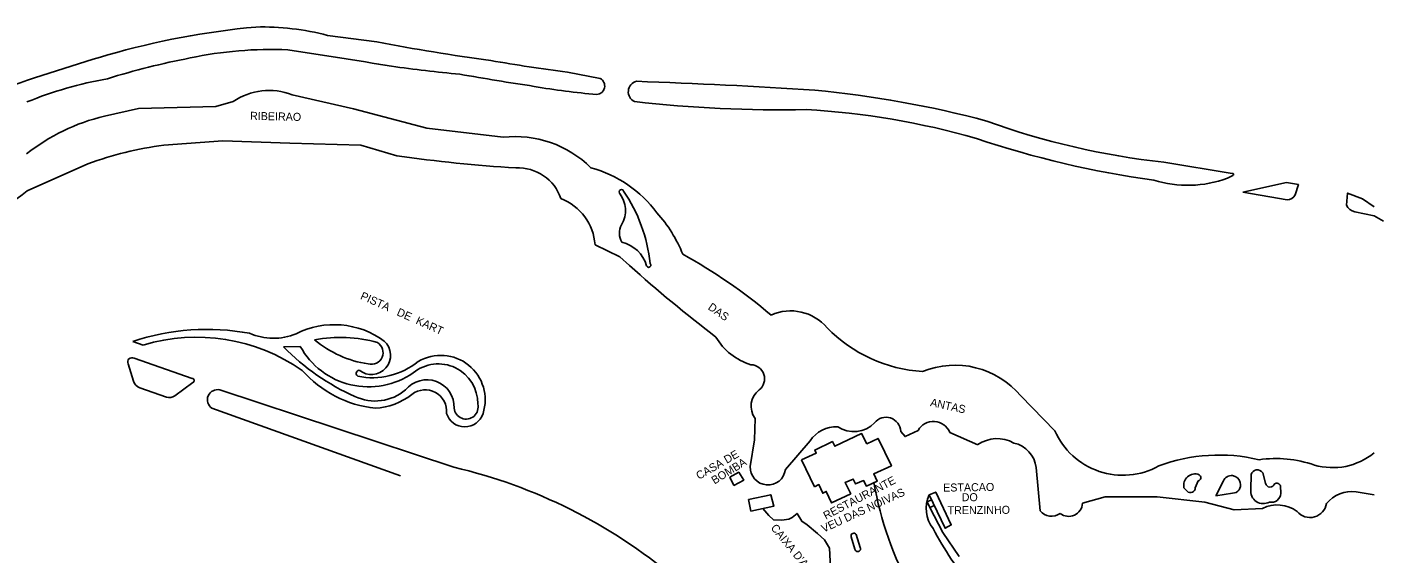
# Model space of a CAD drawing. Extents: x 325899 to 363134, y 7578590 to 7592502.
# Drawn here: x 333008 to 333681, y 7591049 to 7591312 of the extents above; entities that cross this region are included whole.
import ezdxf

# ---------------------------------------------------------------- set-up
doc = ezdxf.new("R2010")
doc.units = 0
for name, color, linetype in [('EDIFEXISTENT', 7, 'Continuous'), ('EDIFIDENTIF', 7, 'Continuous'), ('EDIFOBRAEXIS', 7, 'Continuous')]:
    doc.layers.add(name, color=color, linetype=linetype)

msp = doc.modelspace()

# ---------------------------------------------------------------- linework, layer by layer
at = {"layer": 'EDIFEXISTENT'}
for points in [[(333395.34, 7591095.94), (333402.65, 7591099.32), (333401.9, 7591100.79), (333410.77, 7591105.01), (333412, 7591102.66), (333425.3, 7591109.03), (333428.02, 7591103.98), (333433.53, 7591106.58), (333440.23, 7591092.99), (333431.36, 7591088.94), (333433.16, 7591085.33), (333427.7, 7591082.77), (333426.36, 7591085.58), (333422.22, 7591083.85), (333421.18, 7591086.32), (333417.11, 7591084.62), (333419.89, 7591078.99), (333410.27, 7591074.4), (333407.66, 7591080.14), (333405.94, 7591079.18), (333404.03, 7591083.51), (333401.79, 7591082.5)], [(333401.79, 7591082.5), (333395.34, 7591095.94)], [(333359.5, 7591087.3), (333363.97, 7591089.69), (333366.41, 7591085.83), (333361.49, 7591083.06)], [(333361.49, 7591083.06), (333359.5, 7591087.3)], [(333368.83, 7591076.13), (333379.93, 7591078.43), (333381.51, 7591072.71), (333369.95, 7591070.34)], [(333369.95, 7591070.34), (333368.83, 7591076.13)], [(333460.26, 7591076.01), (333458.07, 7591074.91), (333459.38, 7591072.06), (333461.69, 7591073.03)], [(333459.13, 7591078.4), (333467.07, 7591061.72), (333470.15, 7591063.37), (333462.39, 7591079.84), (333459.13, 7591078.4)]]:
    msp.add_lwpolyline(points, dxfattribs=at)
at = {"layer": 'EDIFOBRAEXIS'}
for points in [[(333158.53, 7591307.9), (333183.07, 7591304.69)], [(333278.34, 7591289.56), (333294.69, 7591286.39)], [(333140.77, 7591278.3), (333171.51, 7591271.3), (333208.15, 7591261.49), (333246.15, 7591257.01)], [(333046.95, 7591267.57), (333064.01, 7591271.32), (333064.01, 7591271.32), (333102.7, 7591272.4), (333111.36, 7591274.89)], [(333076.62, 7591253.08), (333106.2, 7591255.31), (333106.2, 7591255.31), (333139.69, 7591254.02), (333139.69, 7591254.02), (333175.04, 7591253.12), (333193.17, 7591247.78)], [(333008.43, 7591230.2), (333008.43, 7591230.2), (333038.73, 7591243.79)], [(333576.37, 7591244.55), (333610.55, 7591238.93)], [(333610.89, 7591237.92), (333608.11, 7591236.53)], [(333615.84, 7591229.59), (333637.59, 7591234.42), (333643.58, 7591233.4), (333642.02, 7591228.19)], [(333637.91, 7591225.75), (333615.84, 7591229.59)], [(333667.58, 7591223.06), (333668.19, 7591229.12), (333675.62, 7591226.24), (333681.39, 7591222.22)], [(333681.39, 7591217.78), (333671.76, 7591219.84)], [(333686.13, 7591215.08), (333681.39, 7591217.78)], [(333292.13, 7591203.32), (333304.47, 7591197.37), (333309.35, 7591192.9)], [(333408.08, 7591161.9), (333408.08, 7591161.9)], [(333061.14, 7591155.03), (333066.38, 7591153.24)], [(333136.53, 7591152.3), (333144.84, 7591152.57)], [(333061.47, 7591135.2), (333058.89, 7591143.88)], [(333061.79, 7591146.66), (333090.85, 7591136.59)], [(333091.22, 7591134.49), (333082.19, 7591127.95)], [(333078.01, 7591127.21), (333064.71, 7591131.93)], [(333104.68, 7591130.83), (333221.58, 7591092.24)], [(333504.93, 7591127.84), (333504.93, 7591127.84), (333521.92, 7591110.44)], [(333194.9, 7591088), (333100.72, 7591121.67)], [(333372.08, 7591116.61), (333371.81, 7591105.83), (333369.71, 7591092.55)], [(333444.89, 7591110.14), (333447.07, 7591107.49), (333453.53, 7591110.64)], [(333469.42, 7591109.64), (333483.39, 7591103.48)], [(333387.27, 7591091.06), (333399.56, 7591105.38)], [(333512.56, 7591092.09), (333514.55, 7591070.45)], [(333619.81, 7591081.09), (333619.93, 7591088.57)], [(333625.76, 7591089.48), (333627.17, 7591084.19)], [(333587.99, 7591080.26), (333586.41, 7591081.92)], [(333593.56, 7591085.43), (333592.01, 7591081.97)], [(333602.31, 7591077.99), (333606.13, 7591085.47)], [(333634.58, 7591082.87), (333634.79, 7591079.17)], [(333535.72, 7591074.19), (333535.72, 7591074.19), (333546.96, 7591077.36), (333573.08, 7591077.44), (333596.78, 7591074.8), (333611.44, 7591070.98), (333625.59, 7591071.65)], [(333610.62, 7591079.24), (333602.31, 7591077.99)], [(333672.42, 7591079.97), (333681.39, 7591078.36)], [(333415.39, 7591001.91), (333414.42, 7591006.63), (333413.04, 7591009), (333411.63, 7591013.2), (333411.34, 7591016.7), (333412.19, 7591020.52), (333413.53, 7591026.91), (333411.93, 7591036.33), (333410.02, 7591038.32), (333409.63, 7591040.66), (333409.69, 7591045.33), (333409.23, 7591051.77), (333406.75, 7591055.98), (333403.35, 7591059.05), (333398.08, 7591063.5), (333395.51, 7591065.25), (333393.13, 7591069.12), (333390.63, 7591067.16), (333388.9, 7591066.21), (333385.42, 7591065.8), (333381.34, 7591066.01), (333378.97, 7591068.03), (333376.06, 7591071.59)], [(333459.38, 7591072.06), (333465.92, 7591059.68), (333474.02, 7591047.6)], [(333421.96, 7591051.33), (333420.13, 7591057.53)], [(333422.58, 7591058.58), (333424.66, 7591052.17)]]:
    msp.add_lwpolyline(points, dxfattribs=at)
for centre, radius, start, end in [((333160.18, 7590908.67), 405.16, 95.30659, 105.98382), ((333125.64, 7591181.99), 130.13, 75.36146, 91.28881), ((333385.66, 7592363.18), 1077.71, 259.16484, 262.23473), ((333407.38, 7590090.64), 1259.69, 106.54711, 109.33146), ((333163.61, 7590915.04), 388.66, 100.94658, 107.23593), ((333130.12, 7591108.09), 192.79, 87.47221, 102.06812), ((332778.16, 7588857.19), 2469.95, 80.39191, 81.60842), ((333299.06, 7592071.35), 786.4, 262.0588, 264.56148), ((333371.9, 7592037.02), 753.29, 259.91953, 262.86508), ((333082.09, 7591094.16), 195, 99.93372, 112.24518), ((333517.28, 7592974.3), 1711.04, 260.14848, 261.41181), ((333317.1, 7591589.55), 312.04, 259.78717, 265.56675), ((333292.76, 7591282.64), 4.21, 272.95434, 62.70336), ((333314.13, 7591279.75), 5.38, 103.65875, 245.47768), ((333200.26, 7588118.14), 3168.84, 86.35167, 87.96373), ((333129.33, 7591248.38), 32.03, 69.07193, 124.12279), ((333352.9, 7590761.29), 521.57, 75.00604, 84.60861), ((333384.64, 7591906.84), 636.15, 263.43368, 271.17087), ((333376.07, 7590884.3), 387.12, 74.01508, 86.8061), ((333070.59, 7591169.23), 101.14, 103.52176, 128.22617), ((333617.39, 7591622.19), 379.86, 250.05913, 263.80106), ((333252.28, 7591203.59), 53.77, 45.31817, 96.54725), ((333639.33, 7591722.29), 491.48, 251.41409, 262.04911), ((333100.66, 7591073.12), 181.56, 97.60808, 109.94372), ((333301.63, 7592012.88), 772.75, 261.93133, 266.36069), ((333253.65, 7591219.02), 22.7, 18.96196, 92.69349), ((333273.91, 7591182.86), 61.14, 36.52653, 74.66366), ((333588.25, 7591291.01), 57.98, 253.05209, 290.03075), ((333610.67, 7591238.41), 0.536, 293.96776, 102.91088), ((332961.7, 7591289.24), 75.3, 270.45361, 308.35753), ((333305.32, 7591229.72), 1.2, 22.52, 209.85126), ((333293.36, 7591220.41), 13.97, 329.42982, 38.59316), ((333240.47, 7591185.61), 79.61, 6.02662, 34.04993), ((333265.53, 7591201.51), 26.66, 3.87942, 68.92641), ((333637.5, 7591231.14), 5.4, 274.39098, 326.9485), ((333672.66, 7591225.34), 5.57, 204.21957, 260.70754), ((333272.7, 7591173.32), 68.15, 21.77652, 42.37131), ((333313.25, 7591209.03), 8.95, 151.43528, 209.76815), ((333301.66, 7591188.09), 16.93, 16.18151, 76.96834), ((333204.95, 7590961), 271.34, 49.79331, 61.12408), ((333810.15, 7591755.7), 753.36, 228.33619, 232.59754), ((333318.95, 7591193.13), 1.08, 197.15189, 50.7088), ((333389.88, 7591146.44), 23.88, 40.34218, 114.15154), ((333161.82, 7591121.21), 42.2, 53.65863, 116.88573), ((333460.37, 7591212.97), 73.09, 224.32044, 266.36881), ((333098.32, 7591043.3), 117.75, 79.61762, 108.40536), ((333093.01, 7591064.95), 92.22, 55.09639, 106.78392), ((333131.47, 7591186.2), 29.59, 246.2207, 292.39565), ((333165.01, 7591089.95), 67.12, 74.05413, 101.18356), ((333186.95, 7591198.05), 54.84, 230.40184, 261.41654), ((333180.35, 7591148.13), 9.59, 230.7496, 47.48402), ((333180.32, 7591149.5), 5.89, 254.70113, 57.83885), ((333379.14, 7591172.86), 30.84, 210.43592, 252.80942), ((333219.29, 7591233.3), 115.8, 224.38201, 245.98879), ((333178.98, 7591171.31), 38.95, 208.76989, 304.8553), ((333215.05, 7591125.88), 22.21, 341.90395, 120.41216), ((333061.04, 7591144.85), 2.36, 139.25384, 204.38518), ((333060.76, 7591144.3), 2.57, 66.47544, 125.81606), ((333180.79, 7591173.65), 36.73, 258.74001, 308.82006), ((333213.77, 7591124.09), 19.75, 359.15107, 129.38718), ((333369.86, 7591136.42), 6.99, 307.19597, 88.59275), ((333471.97, 7591100.15), 43.05, 40.03843, 112.14744), ((333066.25, 7591136.7), 5.01, 197.39592, 252.13682), ((333090.74, 7591135.49), 1.11, 295.70977, 84.30901), ((333188.73, 7591178.82), 57.51, 221.67151, 263.63901), ((333174.45, 7591139.05), 1.65, 95.9203, 239.79215), ((333208.08, 7591122.23), 13.67, 357.90346, 140.88379), ((333079.35, 7591131.81), 4.79, 253.76041, 306.37225), ((333103.51, 7591125.9), 5.07, 76.6024, 236.62784), ((333182.22, 7591148.91), 23.63, 244.82048, 310.20103), ((333180.39, 7591154.5), 32.9, 273.42413, 307.98402), ((333207.27, 7591120.12), 10.74, 354.49022, 128.11362), ((333380.53, 7591122.69), 10.4, 128.28669, 215.75189), ((333227.72, 7591122.25), 6, 184.97713, 14.9377), ((333227.08, 7591121.94), 9.56, 197.33804, 341.93639), ((333421.43, 7591124.29), 14.31, 235.73909, 316.44316), ((333437.53, 7591109.81), 7.36, 2.57005, 141.16356), ((333461.23, 7591106.2), 8.88, 22.78267, 150.04651), ((333413.01, 7591096.16), 16.31, 88.70139, 145.55014), ((333555.88, 7591125.25), 37.05, 203.55052, 298.96773), ((333493.05, 7591089.68), 16.85, 60.23777, 124.98203), ((333498.31, 7591090.28), 14.37, 7.24845, 77.53099), ((333604, 7591012.42), 85.89, 76.57667, 110.56923), ((333632.33, 7591037.9), 58.66, 70.85659, 98.22901), ((333660.77, 7591124.54), 32.54, 253.57792, 309.32306), ((333161, 7590833.65), 265.59, 50.05974, 76.81333), ((333378.52, 7591092.16), 8.82, 177.47267, 352.82965), ((333591.95, 7591083.18), 5.69, 68.73874, 192.70627), ((333593.15, 7591087.05), 1.67, 284.02618, 58.84985), ((333610.13, 7591083.66), 4.39, 11.70941, 155.55827), ((333623.06, 7591087.66), 3.25, 33.89457, 163.79357), ((333602.18, 7591114.01), 173.19, 189.78995, 208.81621), ((333589.69, 7591081.85), 2.32, 223.00916, 2.94728), ((333610.66, 7591083.24), 4, 269.45475, 19.0992), ((333626.05, 7591080.32), 6.29, 173.00486, 298.90187), ((333629.46, 7591084.6), 2.33, 190.26441, 342.89231), ((333632.78, 7591082.41), 1.86, 14.38963, 126.03097), ((333473.84, 7591071.57), 16.22, 155.08935, 217.6997), ((333528.73, 7591074.69), 7.01, 233.15265, 355.88243), ((333630.15, 7591079.34), 4.64, 256.83162, 357.94057), ((333649.38, 7591075.45), 8.35, 219.83736, 350.82187), ((333670.27, 7591063.76), 16.35, 82.459, 140.65688), ((333520.29, 7591075.28), 7.51, 220.06036, 304.3049), ((333633.01, 7591056.57), 16.81, 53.65632, 116.20704), ((333608.91, 7591139.36), 167.08, 207.72043, 219.94087), ((333421.4, 7591057.96), 1.34, 27.66357, 198.71582), ((333423.38, 7591051.53), 1.43, 188.09552, 26.60032)]:
    msp.add_arc(centre, radius, start, end, dxfattribs=at)

# ---------------------------------------------------------------- texts
at = {"layer": 'EDIFIDENTIF'}
for s, rotation, p in [('RIBEIRAO', 358.66284, (333119.7, 7591265.77)), ('PISTA   DE  KART', 336.00348, (333174.52, 7591176.35)), ('DAS', 324.92621, (333348.22, 7591171.36)), ('ANTAS', 347.89687, (333459.36, 7591122.79)), ('CASA DE', 29.94302, (333344.06, 7591085.87)), ('BOMBA', 31.65649, (333351.82, 7591083.56)), ('RESTAURANTE', 27.63329, (333407.49, 7591065.94)), ('VEU DAS NOIVAS', 24.73371, (333406.34, 7591059.47)), ('ESTACAO', 0.80701, (333466.08, 7591080.02)), ('DO', 0.17449, (333475.35, 7591075.24)), ('TRENZINHO', 0.42883, (333468.31, 7591068.73)), ("CAIXA D'AGUA", 309.2265, (333379.69, 7591061.82))]:
    msp.add_text(s, height=4, rotation=rotation, dxfattribs=at).set_placement(p)

doc.saveas('drawing.dxf')
